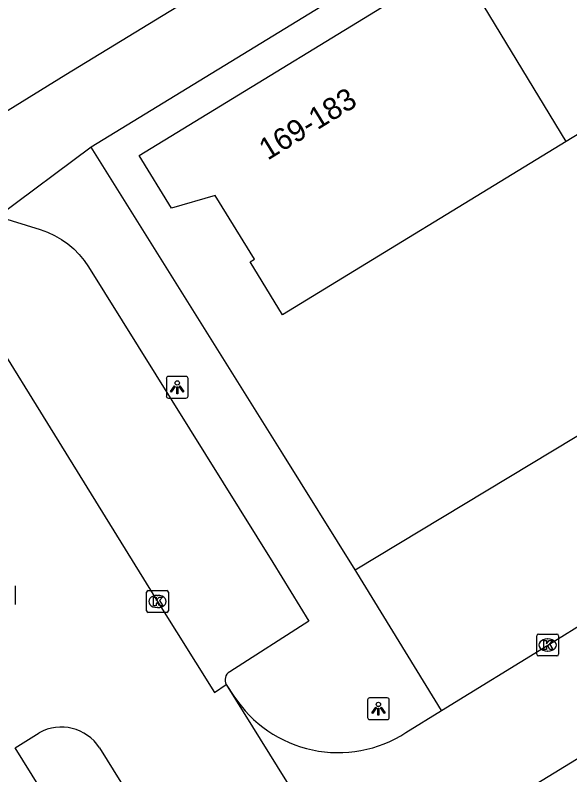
# Model space of a CAD drawing. Extents: x 159888 to 160757, y 384031 to 384746.
# Drawn here: x 160098.43 to 160123.93, y 384569.53 to 384604.42 of the extents above; entities that cross this region are included whole.
import ezdxf

# ---------------------------------------------------------------- set-up
doc = ezdxf.new("R2010")
doc.units = 0
for name, color, linetype in [('IMGEO_Groenvoorziening', 7, 'Continuous'), ('IMGEO_Kolk', 7, 'Continuous'), ('IMGEO_Lichtpunt', 7, 'Continuous'), ('IMGEO_Pand', 7, 'Continuous'), ('IMGEO_Pand_nummerreeks', 7, 'Continuous'), ('IMGEO_Rijbaan_lokaal_open', 7, 'Continuous'), ('IMGEO_Voetpad_open', 7, 'Continuous')]:
    doc.layers.add(name, color=color, linetype=linetype)

msp = doc.modelspace()

# ---------------------------------------------------------------- linework, layer by layer
at = {"layer": 'IMGEO_Groenvoorziening'}
msp.add_lwpolyline([(160114.059, 384578.949), (160127.142, 384586.832), (160189.258, 384625.337)], dxfattribs=at)
at = {"layer": 'IMGEO_Kolk'}
for p, q in [((160098.431, 384578.205), (160098.431, 384577.353)), ((160104.473, 384577.063), (160104.473, 384577.915)), ((160104.548, 384577.989), (160105.4, 384577.989)), ((160104.961, 384577.769), (160104.986, 384577.769)), ((160105.474, 384577.915), (160105.474, 384577.063)), ((160105.4, 384576.989), (160104.548, 384576.989)), ((160104.984, 384577.209), (160104.959, 384577.209)), ((160122.483, 384575.988), (160123.335, 384575.988)), ((160122.408, 384575.062), (160122.408, 384575.914)), ((160122.896, 384575.768), (160122.921, 384575.768)), ((160123.409, 384575.914), (160123.409, 384575.062)), ((160123.335, 384574.988), (160122.483, 384574.988)), ((160122.919, 384575.208), (160122.894, 384575.208))]:
    msp.add_line(p, q, dxfattribs=at)
for points in [[(160098.431, 384578.205), (160098.431, 384577.353)], [(160104.473, 384577.063), (160104.473, 384577.915)], [(160104.548, 384577.989), (160105.4, 384577.989)], [(160104.794, 384577.689), (160104.917, 384577.689), (160104.917, 384577.538), (160105.047, 384577.689), (160105.211, 384577.689), (160105.065, 384577.538), (160105.218, 384577.289), (160105.066, 384577.289), (160104.981, 384577.453), (160104.917, 384577.386), (160104.917, 384577.289), (160104.794, 384577.289), (160104.794, 384577.689)], [(160105.474, 384577.915), (160105.474, 384577.063)], [(160105.4, 384576.989), (160104.548, 384576.989)], [(160122.483, 384575.988), (160123.335, 384575.988)], [(160122.408, 384575.062), (160122.408, 384575.914)], [(160122.729, 384575.688), (160122.852, 384575.688), (160122.852, 384575.537), (160122.982, 384575.688), (160123.146, 384575.688), (160123, 384575.537), (160123.153, 384575.288), (160123.001, 384575.288), (160122.916, 384575.452), (160122.852, 384575.385), (160122.852, 384575.288), (160122.729, 384575.288), (160122.729, 384575.688)], [(160123.409, 384575.914), (160123.409, 384575.062)], [(160123.335, 384574.988), (160122.483, 384574.988)]]:
    msp.add_lwpolyline(points, dxfattribs=at)
for centre, start, end in [((160104.55, 384577.913), 91.552, 178.448), ((160104.55, 384577.913), 91.552, 178.448), ((160105.398, 384577.913), 1.552, 88.448), ((160105.398, 384577.913), 1.552, 88.448), ((160104.55, 384577.065), 181.552, 268.448), ((160104.55, 384577.065), 181.552, 268.448), ((160105.398, 384577.065), 271.552, 358.448), ((160105.398, 384577.065), 271.552, 358.448), ((160122.485, 384575.912), 91.552, 178.448), ((160122.485, 384575.912), 91.552, 178.448), ((160123.333, 384575.912), 1.552, 88.448), ((160123.333, 384575.912), 1.552, 88.448), ((160122.485, 384575.064), 181.552, 268.448), ((160122.485, 384575.064), 181.552, 268.448), ((160123.333, 384575.064), 271.552, 358.448), ((160123.333, 384575.064), 271.552, 358.448)]:
    msp.add_arc(centre, 0.0765, start, end, dxfattribs=at)
for centre, major_axis, ratio, start_param, end_param in [((160104.96, 384577.489), (-0.387, 0.002), 0.722429, 4.712389, 7.853982), ((160104.985, 384577.489), (-0.39, 0.002), 0.717154, 1.570796, 4.712389), ((160122.895, 384575.488), (-0.387, 0.002), 0.722429, 4.712389, 7.853982), ((160122.92, 384575.488), (-0.39, 0.002), 0.717154, 1.570796, 4.712389)]:
    msp.add_ellipse(centre, major_axis=major_axis, ratio=ratio, start_param=start_param, end_param=end_param, dxfattribs=at)
at = {"layer": 'IMGEO_Lichtpunt'}
for p, q in [((160106.282, 384587.827), (160105.474, 384587.827)), ((160106.282, 384587.827), (160105.474, 384587.827)), ((160105.38, 384587.732), (160105.38, 384586.925)), ((160105.38, 384587.732), (160105.38, 384586.925)), ((160106.376, 384586.925), (160106.376, 384587.732)), ((160106.376, 384586.925), (160106.376, 384587.732)), ((160105.474, 384586.831), (160106.282, 384586.831)), ((160105.474, 384586.831), (160106.282, 384586.831)), ((160114.632, 384572.964), (160114.632, 384572.157)), ((160114.632, 384572.964), (160114.632, 384572.157)), ((160115.534, 384573.059), (160114.726, 384573.059)), ((160115.534, 384573.059), (160114.726, 384573.059)), ((160115.628, 384572.157), (160115.628, 384572.964)), ((160115.628, 384572.157), (160115.628, 384572.964)), ((160114.726, 384572.063), (160115.534, 384572.063)), ((160114.726, 384572.063), (160115.534, 384572.063))]:
    msp.add_line(p, q, dxfattribs=at)
for points in [[(160105.754, 384587.396), (160105.793, 384587.368), (160105.605, 384587.106), (160105.567, 384587.133), (160105.754, 384587.396)], [(160105.856, 384587.348), (160105.903, 384587.348), (160105.903, 384587.026), (160105.856, 384587.026), (160105.856, 384587.348)], [(160105.966, 384587.368), (160106.004, 384587.395), (160106.191, 384587.133), (160106.152, 384587.105), (160105.966, 384587.368)], [(160115.006, 384572.628), (160115.045, 384572.6), (160114.857, 384572.338), (160114.819, 384572.365), (160115.006, 384572.628)], [(160115.108, 384572.58), (160115.155, 384572.58), (160115.155, 384572.258), (160115.108, 384572.258), (160115.108, 384572.58)], [(160115.218, 384572.6), (160115.256, 384572.627), (160115.443, 384572.365), (160115.404, 384572.337), (160115.218, 384572.6)]]:
    msp.add_lwpolyline(points, dxfattribs=at)
for centre in [(160105.879, 384587.53), (160115.131, 384572.762)]:
    msp.add_circle(centre, 0.0994, dxfattribs=at)
for centre, start, end in [((160105.474, 384587.732), 90, 180), ((160105.474, 384587.732), 90, 180), ((160106.282, 384587.732), 0, 90), ((160106.282, 384587.732), 0, 90), ((160105.474, 384586.925), 180, 270), ((160105.474, 384586.925), 180, 270), ((160106.282, 384586.925), 270, 0), ((160106.282, 384586.925), 270, 360), ((160114.726, 384572.964), 90, 180), ((160114.726, 384572.964), 90, 180), ((160115.534, 384572.964), 0, 90), ((160115.534, 384572.964), 0, 90), ((160114.726, 384572.157), 180, 270), ((160114.726, 384572.157), 180, 270), ((160115.534, 384572.157), 270, 0), ((160115.534, 384572.157), 270, 360)]:
    msp.add_arc(centre, 0.0946, start, end, dxfattribs=at)
at = {"layer": 'IMGEO_Pand'}
for points in [[(160123.758, 384598.618), (160110.725, 384590.659), (160109.229, 384593.088), (160109.425, 384593.208), (160107.62, 384596.134), (160105.624, 384595.56), (160104.129, 384597.973), (160118.738, 384606.9)], [(160123.758, 384598.618), (160118.738, 384606.9)], [(160136.756, 384606.556), (160123.758, 384598.618)]]:
    msp.add_lwpolyline(points, dxfattribs=at)
at = {"layer": 'IMGEO_Rijbaan_lokaal_open'}
for points in [[(160119.095, 384567.099), (160125.73, 384571.163), (160142.314, 384581.429), (160157.202, 384590.641), (160174.681, 384601.465), (160189.904, 384610.881), (160190.488, 384611.242), (160192.716, 384612.554)], [(160092.437, 384597.729), (160104.973, 384577.489), (160107.592, 384573.311), (160108.137, 384573.672)], [(160118.034, 384572.48), (160122.909, 384575.488), (160128.843, 384579.15), (160136.097, 384583.626), (160140.332, 384586.252)], [(160108.137, 384573.672), (160108.487, 384573.145)], [(160108.137, 384573.672), (160117.159, 384559.167)], [(160116.393, 384571.466), (160118.034, 384572.48)], [(160098.429, 384570.771), (160099.535, 384571.453)], [(160102.306, 384570.763), (160113.563, 384552.653), (160125.049, 384534.359), (160139.118, 384511.747), (160144.747, 384502.719)]]:
    msp.add_lwpolyline(points, dxfattribs=at)
for centre, radius, start, end in [((160113.279, 384576.256), 5.713, 212.9916, 303.0289), ((160100.553, 384569.631), 2.087, 32.8565, 119.1781)]:
    msp.add_arc(centre, radius, start, end, dxfattribs=at)
at = {"layer": 'IMGEO_Voetpad_open'}
for points in [[(160183.001, 384647.819), (160137.178, 384619.898), (160101.924, 384598.362)], [(160096.731, 384599.212), (160100.758, 384601.692), (160116.343, 384611.201), (160132.533, 384621.049)], [(160101.924, 384598.362), (160097.641, 384595.169)], [(160114.059, 384578.949), (160110.734, 384584.277), (160101.924, 384598.362)], [(160097.641, 384595.169), (160099.581, 384594.573), (160099.919, 384594.452), (160100.244, 384594.301), (160100.554, 384594.122), (160100.847, 384593.916), (160101.12, 384593.684), (160101.372, 384593.429), (160101.6, 384593.153), (160101.802, 384592.857), (160110.282, 384579.275), (160111.937, 384576.581), (160108.292, 384574.259)], [(160118.034, 384572.48), (160114.138, 384578.822), (160114.059, 384578.949)], [(160109.97, 384552.226), (160098.429, 384570.771)]]:
    msp.add_lwpolyline(points, dxfattribs=at)
msp.add_arc((160108.507, 384573.888), 0.429, 120.1538, 210.263, dxfattribs=at)

# ---------------------------------------------------------------- texts
at = {"layer": 'IMGEO_Pand_nummerreeks'}
msp.add_text('169-183', height=1, rotation=31.4875, dxfattribs=at).set_placement((160110.038, 384597.733))

doc.saveas('drawing.dxf')
